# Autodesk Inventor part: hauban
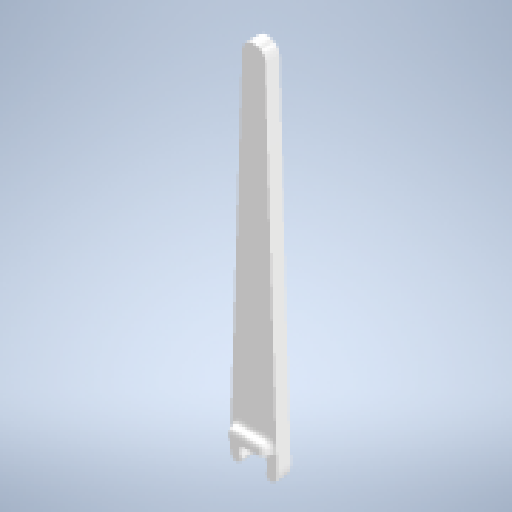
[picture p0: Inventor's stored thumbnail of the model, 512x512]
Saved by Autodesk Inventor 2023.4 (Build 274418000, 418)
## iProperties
Created: 2023-11
Part Number: hauban
Material: Plastique ABS
Document SubType Name: Modeling
Designer: mel
Density: 1.06 g/cm^3
Appearance: Lisse - Orange clair
Author: mel
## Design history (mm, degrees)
sketch "Esquisse3"
  geometry: L1 (-1, 3)-(-9, 3) reference; L2 (-3.002, 75.08)-(-0.004, 0.2); L3 (-6.998, 75.08)-(-9.996, 0.2); L4 (-3.197, 3)-(-6.803, 3); A1 r 3.5 centre (-5, 0) between (-6.803, 3) and (-3.197, 3) reference; A2 r 5 centre (-5, 0) between (-9, 3) and (-1, 3) reference; A3 r 0.75 centre (-1.2, -1.903) between (-1.871, -1.567) and (-0.529, -2.239); A4 r 0.75 centre (-8.8, -1.903) between (-9.471, -2.239) and (-8.129, -1.567); A5 r 2 centre (-5, 75) between (-3.002, 75.08) and (-6.998, 75.08); A6 r 3.5 centre (-5, 0) between (-6.803, 3) and (-8.129, -1.567); A7 r 3.5 centre (-5, 0) between (-1.871, -1.567) and (-3.197, 3); A8 r 5 centre (-5, 0) between (-0.529, -2.239) and (-0.004, 0.2); A9 r 5 centre (-5, 0) between (-9.996, 0.2) and (-9.471, -2.239); 5 further points
  constraints: 16 point on circle, 8 end point, 8 tangent, 7 centre point, 2 coincident, 2 point on line, 1 collinear
  dimensions: "d11" = 3.8 horizontal distance of A3.centre A1.centre; "d12" = 3.8 horizontal distance of A4.centre A1.centre (= d11); "d13" = 4 diameter of A5; "d14" = 75 distance of A1.centre A5.centre; "d17" = 5 horizontal distance of point (0, 0) A5.centre
extrude "Extrusion3" join sketch "Esquisse3" distance "d15" = 3; taper "d16" = 0 deg
node "Solide1"
node "Référence3"
node "Référence4"
node "Référence5"
